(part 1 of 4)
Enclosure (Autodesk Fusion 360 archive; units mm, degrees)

design "BOX" references "IO_BOARD"
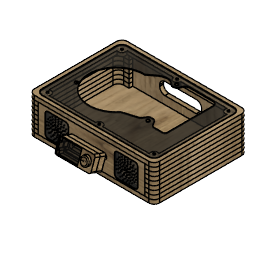
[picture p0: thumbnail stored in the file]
part number: 2026-06-03-19-10-17-454
part number: 2026-06-04-17-30-21-244
part number: 2026-06-04-17-30-21-255
part number: 2026-06-04-17-30-21-260
part number: 2026-06-04-17-30-21-264
part number: 2026-06-04-17-30-21-269
part number: 2026-06-04-17-30-21-274
part number: 2026-06-04-17-30-21-278
part number: 2026-06-04-17-30-21-283
part number: 2026-06-04-17-30-21-289
part number: 2026-06-04-17-30-21-295
part number: 2026-06-04-17-30-21-300
part number: 2026-06-04-17-30-21-306
part number: 2026-06-04-17-30-21-312
part number: 2026-06-04-17-30-21-318
part number: 2026-06-04-17-30-21-324
part number: 2026-06-04-17-30-21-331
part number: 2026-06-04-17-30-21-338
part number: 2026-06-04-17-30-21-345
part number: 2026-06-04-17-30-21-352
parameter "ply" = 11.21
parameter "acrylic" = 2
parameter "viewing" = 70
parameter "top_mount" = 6
parameter "acr_kerf" = 0.75
parameter "prt_tol" = 0.2
sketch "Sketch1" plane through (0, 0, 0) normal (0, 0, 1) x axis (1, 0, 0)
  line L1 (-175, 130) -> (175, 130)
  line L2 (-175, -130) -> (-175, 130)
  line L3 (175, -130) -> (-175, -130)
  line L4 (175, 130) -> (175, -130)
  line L5 (-175, -130) -> (175, 130)
  line L6 (175, -130) -> (-175, 130)
  point P6 (0, 0)
  point P1 (0, 0)
  point P4 (-175, -130)
  point P5 (175, -130)
  point P3 (-175, 130)
  horizontal L1
  perpendicular L1 L2
  parallel L1 L3
  parallel L2 L4
  coincident L5 P6
  coincident L6 P6
  coincident P1 P6
  dimension "d1" distance P4 P5 = 350
  dimension "d2" distance P3 P4 = 260
extrude "Extrude1" new body sketch "Sketch1" profile of L1 L2 L3 L4 along normal blind 11.21 (= "ply") bodies "BOTTOM"
sketch "Sketch2" plane through (0, 0, 11.21) normal (0, 0, 1) x axis (-1, 0, 0)
  line L1 (-175, -130) -> (-175, 130)
  line L2 (175, -130) -> (-175, -130)
  line L3 (175, 130) -> (175, -130)
  line L4 (-175, 130) -> (175, 130)
  line L5 (175, 130) -> (-175, 130)
  line L6 (175, -130) -> (175, 130)
  line L7 (-175, -130) -> (175, -130)
  line L8 (-175, 130) -> (-175, -130)
  line L9 (175, -130) -> (-175, 130)
  line L10 (-175, -130) -> (175, 130)
  line L11 (163.79, 118.79) -> (-163.79, 118.79)
  line L12 (163.79, -118.79) -> (163.79, 118.79)
  line L13 (-163.79, -118.79) -> (163.79, -118.79)
  line L14 (-163.79, 118.79) -> (-163.79, -118.79)
  line L15 (-163.79, -118.79) -> (163.79, -118.79)
  line L16 (-163.79, -108.79) -> (-163.79, -118.79)
  line L17 (163.79, -108.79) -> (-163.79, -108.79)
  line L18 (163.79, -118.79) -> (163.79, -108.79)
  line L19 (-163.79, 118.79) -> (163.79, 118.79)
  line L20 (-163.79, 108.79) -> (-163.79, 118.79)
  line L21 (163.79, 108.79) -> (-163.79, 108.79)
  line L22 (163.79, 118.79) -> (163.79, 108.79)
  line L23 (133.79, -108.79) -> (133.79, -118.79)
  line L24 (0, 130) -> (0, -130)
  line L25 (-175, 0) -> (175, 0)
  line L26 (148.79, -118.79) -> (148.79, -130)
  line L27 (-133.79, -108.79) -> (-133.79, -118.79)
  line L28 (-148.79, -118.79) -> (-148.79, -130)
  line L29 (148.79, 118.79) -> (148.79, 130)
  line L30 (133.79, 108.79) -> (133.79, 118.79)
  line L31 (-148.79, 118.79) -> (-148.79, 130)
  line L32 (-133.79, 108.79) -> (-133.79, 118.79)
  point P10 (0, 0)
  point P2 (-175, 130)
  point P6 (-175, 130)
  point P1 (0, 0)
  point P21 (133.79, -118.79)
  point P22 (133.79, -108.79)
  point P23 (0, -130)
  point P24 (0, 130)
  point P25 (175, 0)
  point P26 (-175, 0)
  point P27 (148.79, -130)
  point P28 (148.79, -118.79)
  point P29 (-133.79, -118.79)
  point P30 (-133.79, -108.79)
  point P31 (-148.79, -130)
  point P32 (-148.79, -118.79)
  point P35 (133.79, 118.79)
  point P36 (133.79, 108.79)
  point P33 (148.79, 130)
  point P34 (148.79, 118.79)
  point P39 (-133.79, 118.79)
  point P40 (-133.79, 108.79)
  point P37 (-148.79, 130)
  point P38 (-148.79, 118.79)
  point P13 (163.79, -118.79)
  point P17 (163.79, -108.79)
  point P12 (163.79, 118.79)
  point P20 (163.79, 108.79)
  horizontal L5
  perpendicular L5 L6
  parallel L5 L7
  parallel L6 L8
  coincident L9 P10
  coincident L10 P10
  coincident P2 P6
  coincident P1 P10
  horizontal L15
  vertical L16
  horizontal L17
  vertical L18
  horizontal L19
  vertical L20
  horizontal L21
  vertical L22
  coincident L13 P21
  coincident L17 P22
  perpendicular L17 L23
  midpoint L7 P23
  midpoint L5 P24
  midpoint L6 P25
  midpoint L8 P26
  collinear L14 L16
  collinear L14 L20
  coincident L7 P27
  coincident L15 P28
  perpendicular L15 L26
  symmetric P21 L24 P29
  symmetric P22 L24 P30
  symmetric L24 P27 P31
  symmetric L24 P28 P32
  symmetric P21 L25 P35
  symmetric P22 L25 P36
  symmetric L25 P27 P33
  symmetric L25 P28 P34
  symmetric L25 P29 P39
  symmetric L25 P30 P40
  symmetric L25 P31 P37
  symmetric L25 P32 P38
  dimension "d6" = 11.21 (= "ply")
  dimension "d7" distance P13 P17 = 10
  dimension "d8" distance P12 P20 = 10
  dimension "d9" distance L18 L23 = 30
  dimension "d10" distance L18 L26 = 15
extrude "Extrude2" new body sketch "Sketch2" profile of L1 L2 L3 L4 L5 L6 L7 L8 L14 L11 L12 L13 L15 L16 L17 L18 L19 L20 L21 L22 L23 L26 L27 L28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 along normal blind 11.21 (= "ply") bodies "L1", "R1"
fillet "Fillet2" radius 15
copy_paste_bodies "CopyPasteBodies1"
move "Move1"
copy_paste_bodies "CopyPasteBodies2"
copy_paste_bodies "CopyPasteBodies3"
move "Move2"
copy_paste_bodies "CopyPasteBodies4"
move "Move3"
copy_paste_bodies "CopyPasteBodies5"
move "Move4"
copy_paste_bodies "CopyPasteBodies6"
move "Move5"
copy_paste_bodies "CopyPasteBodies8"
move "Move7"
sketch "Sketch5" plane through (0, 0, 89.68) normal (0, 0, 1) x axis (-1, 0, 0)
  line L1 (-148.79, -130) -> (-160, -130)
  line L2 (-148.79, -118.79) -> (-148.79, -130)
  line L3 (-133.79, -118.79) -> (-148.79, -118.79)
  line L4 (-133.79, -108.79) -> (-133.79, -118.79)
  line L5 (-148.79, -108.79) -> (-133.79, -108.79)
  line L6 (-163.79, 93.79) -> (-163.79, -93.79)
  line L7 (-133.79, 108.79) -> (-148.79, 108.79)
  line L8 (-133.79, 118.79) -> (-133.79, 108.79)
  line L9 (-148.79, 118.79) -> (-133.79, 118.79)
  line L10 (-148.79, 130) -> (-148.79, 118.79)
  line L11 (-160, 130) -> (-148.79, 130)
  line L12 (-175, -115) -> (-175, 115)
  line L13 (175, 115) -> (175, -115)
  line L14 (148.79, 130) -> (160, 130)
  line L15 (148.79, 118.79) -> (148.79, 130)
  line L16 (133.79, 118.79) -> (148.79, 118.79)
  line L17 (133.79, 108.79) -> (133.79, 118.79)
  line L18 (148.79, 108.79) -> (133.79, 108.79)
  line L19 (163.79, -93.79) -> (163.79, 93.79)
  line L20 (133.79, -108.79) -> (148.79, -108.79)
  line L21 (133.79, -118.79) -> (133.79, -108.79)
  line L22 (148.79, -118.79) -> (133.79, -118.79)
  line L23 (148.79, -130) -> (148.79, -118.79)
  line L24 (160, -130) -> (148.79, -130)
  line L25 (148.79, 118.79) -> (-163, 118.79)
  line L26 (-163.79, 103.79) -> (-163.79, -103.79)
  line L27 (148.79, -118.79) -> (-148.79, -118.79)
  line L28 (163.79, -103.79) -> (163.79, 103.79)
  line L29 (148.79, -130) -> (-148.79, -130)
  line L30 (148.79, -118.79) -> (148.79, -130)
  line L31 (-148.79, -118.79) -> (148.79, -118.79)
  line L32 (-148.79, -130) -> (-148.79, -118.79)
  line L33 (148.79, 118.79) -> (-148.79, 118.79)
  line L34 (148.79, 130) -> (148.79, 118.79)
  line L35 (-148.79, 130) -> (148.79, 130)
  line L36 (-148.79, 118.79) -> (-148.79, 130)
  line L37 (148.79, -108.79) -> (-148.79, -108.79)
  line L38 (153.79, -103.79) -> (153.79, 103.79)
  line L39 (148.79, 108.79) -> (-138.79, 108.79)
  line L40 (-153.79, 93.79) -> (-153.79, -103.79)
  line L41 (0, 130) -> (0, -130)
  arc A1 centre (-160, -115) radius 15 clockwise from (-160, -130) to (-175, -115)
  arc A2 centre (-148.79, -93.79) radius 15 clockwise from (-148.79, -108.79) to (-163.79, -93.79)
  arc A3 centre (-148.79, 93.79) radius 15 clockwise from (-163.79, 93.79) to (-148.79, 108.79)
  arc A4 centre (-160, 115) radius 15 clockwise from (-175, 115) to (-160, 130)
  arc A5 centre (160, -115) radius 15 clockwise from (175, -115) to (160, -130)
  arc A6 centre (160, 115) radius 15 clockwise from (160, 130) to (175, 115)
  arc A7 centre (148.79, 93.79) radius 15 clockwise from (148.79, 108.79) to (163.79, 93.79)
  arc A8 centre (148.79, -93.79) radius 15 clockwise from (163.79, -93.79) to (148.79, -108.79)
  arc A9 centre (-148.79, -103.79) radius 15 clockwise from (-148.79, -118.79) to (-163.79, -103.79)
  arc A10 centre (148.79, -103.79) radius 15 clockwise from (163.79, -103.79) to (148.79, -118.79)
  arc A11 centre (148.79, 103.79) radius 15 clockwise from (148.79, 118.79) to (163.79, 103.79)
  arc A12 centre (148.79, -103.79) radius 5 clockwise from (153.79, -103.79) to (148.79, -108.79)
  arc A13 centre (148.79, 103.79) radius 5 clockwise from (148.79, 108.79) to (153.79, 103.79)
  arc A14 centre (-148.79, -103.79) radius 5 clockwise from (-148.79, -108.79) to (-153.79, -103.79)
  arc A15 centre (-148.79, 103.79) radius 15 clockwise from (-163.79, 103.79) to (-148.79, 118.79)
  arc A16 centre (-138.79, 93.79) radius 15 clockwise from (-153.79, 93.79) to (-138.79, 108.79)
  circle C1 centre (148.79, -103.79) radius 10
  circle C2 centre (148.79, 103.79) radius 10
  circle C3 centre (-148.79, 103.79) radius 10
  circle C4 centre (-148.79, -103.79) radius 10
  circle C5 centre (0, -108.79) radius 10
  circle C6 centre (0, 108.79) radius 10
  point P40 (148.79, -118.79)
  point P45 (148.79, -118.79)
  point P5 (-148.79, -130)
  point P43 (-148.79, -130)
  point P28 (148.79, 130)
  point P49 (148.79, 130)
  point P17 (-148.79, 118.79)
  point P47 (-148.79, 118.79)
  point P79 (0, -130)
  point P80 (0, 130)
  point P81 (0, -108.79)
  point P82 (0, 108.79)
  perpendicular L15 L25
  parallel L6 L26
  collinear L6 L26
  collinear L9 L25
  perpendicular L23 L27
  parallel L13 L28
  collinear L3 L27
  collinear L19 L28
  horizontal L29
  vertical L30
  horizontal L31
  vertical L32
  coincident P40 P45
  coincident P5 P43
  horizontal L33
  vertical L34
  horizontal L35
  vertical L36
  coincident P28 P49
  coincident P17 P47
  tangent L26 A9
  tangent L27 A9
  tangent L27 A10
  tangent L28 A10
  tangent L25 A11
  tangent L28 A11
  equal A10 A11
  concentric A10 A12
  concentric A11 A13
  concentric A9 A14
  tangent L37 A14
  tangent L37 A12
  tangent A12 L38
  tangent L38 A13
  tangent A13 L39
  tangent L40 A14
  coincident P47 L33
  tangent L33 A15
  tangent L26 A15
  equal A10 A15
  tangent L40 A16
  tangent L39 A16
  equal A10 A16
  concentric A12 C1
  concentric A13 C2
  concentric A15 C3
  concentric A9 C4
  midpoint L29 P79
  midpoint L35 P80
  midpoint L37 P81
  coincident L39 P82
  coincident L41 P82
  dimension "d30" radius A9 = 15
  dimension "d31" radius A10 = 15
  dimension "d110" diameter C1 = 20
  dimension "d111" diameter C2 = 20
  dimension "d112" diameter C3 = 20
  dimension "d113" diameter C4 = 20
  dimension "d114" diameter C5 = 20
  dimension "d115" diameter C6 = 20
extrude "Extrude6" new body sketch "Sketch5" profile of A1 L1 L2 L3 L6 L9 L10 L11 A4 L12 A5 L13 A6 L14 L15 L16 L19 L22 L23 L24 L25 L26 L27 L28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 along normal blind 11.21 (= "ply") bodies "TOP"
extrude "Extrude7" add sketch "Sketch5" profile of L3 L4 L5 A2 L6 A3 L7 L8 L9 L16 L17 L18 A7 L19 A8 L20 L21 L22 L25 L26 L27 L28 L37 L38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 along normal blind 9.21 (= "ply - acrylic")
sketch "Sketch6" plane through (0, 0, 98.89) normal (0, 0, 1) x axis (-1, 0, 0)
  line L1 (-10, 108.79) -> (-138.79, 108.79)
  line L2 (-148.79, 118.79) -> (148.79, 118.79)
  line L3 (-163.79, -103.79) -> (-163.79, 103.79)
  line L4 (148.79, -118.79) -> (-148.79, -118.79)
  line L5 (163.79, 103.79) -> (163.79, -103.79)
  line L6 (153.79, -95.1297) -> (153.79, 95.1297)
  line L7 (10, -108.79) -> (140.1297, -108.79)
  line L8 (-153.79, 93.79) -> (-153.79, -95.1297)
  line L9 (140.1297, 108.79) -> (10, 108.79)
  line L10 (-140.1297, -108.79) -> (-10, -108.79)
  arc A1 centre (-148.79, 103.79) radius 15 clockwise from (-163.79, 103.79) to (-148.79, 118.79)
  arc A2 centre (-148.79, -103.79) radius 15 clockwise from (-148.79, -118.79) to (-163.79, -103.79)
  arc A3 centre (148.79, -103.79) radius 15 clockwise from (163.79, -103.79) to (148.79, -118.79)
  arc A4 centre (148.79, 103.79) radius 15 clockwise from (148.79, 118.79) to (163.79, 103.79)
  arc A5 centre (0, 108.79) radius 10 clockwise from (10, 108.79) to (-10, 108.79)
  arc A6 centre (-138.79, 93.79) radius 15 clockwise from (-140.0971, 108.7329) to (-138.79, 108.79)
  arc A7 centre (148.79, 103.79) radius 10 clockwise from (153.79, 95.1297) to (140.1297, 108.79)
  arc A8 centre (148.79, -103.79) radius 10 clockwise from (140.1297, -108.79) to (153.79, -95.1297)
  arc A9 centre (0, -108.79) radius 10 clockwise from (-10, -108.79) to (10, -108.79)
  arc A10 centre (-148.79, -103.79) radius 10 clockwise from (-153.79, -95.1297) to (-140.1297, -108.79)
  arc A11 centre (-138.79, 93.79) radius 15 clockwise from (-153.79, 93.79) to (-153.7329, 95.0971)
  arc A12 centre (-148.79, 103.79) radius 10 clockwise from (-140.0971, 108.7329) to (-153.7329, 95.0971)
extrude "Extrude8" new body sketch "Sketch6" profile of L1 L2 A1 L3 A2 L4 A3 L5 A4 along normal blind 2 (= "acrylic") bodies "ACRYLIC"
sketch "Sketch7" plane through (0, 130, 0) normal (0, 1, 0) x axis (-1, 0, 0)
  line L1 (-160, 78.47) -> (-160, 89.68)
  line L2 (-148.79, 78.47) -> (-160, 78.47)
  line L3 (-148.79, 89.68) -> (-148.79, 78.47)
  line L4 (-148.79, 89.68) -> (-148.79, 78.47)
  line L5 (-148.79, 78.47) -> (-148.79, 67.26)
  line L6 (-148.79, 67.26) -> (-148.79, 56.05)
  line L7 (-148.79, 56.05) -> (-148.79, 44.84)
  line L8 (-148.79, 44.84) -> (-148.79, 33.63)
  line L9 (-148.79, 33.63) -> (-148.79, 22.42)
  line L10 (-148.79, 22.42) -> (-148.79, 11.21)
  line L11 (160, 89.68) -> (-160, 89.68)
  line L12 (160, 11.21) -> (-160, 11.21)
  line L13 (148.79, 33.63) -> (148.79, 22.42)
  line L14 (148.79, 44.84) -> (148.79, 33.63)
  line L15 (148.79, 56.05) -> (148.79, 44.84)
  line L16 (148.79, 67.26) -> (148.79, 56.05)
  line L17 (148.79, 78.47) -> (148.79, 67.26)
  line L18 (148.79, 89.68) -> (148.79, 78.47)
  line L19 (148.79, 22.42) -> (148.79, 11.21)
  line L20 (148.79, 89.68) -> (-148.79, 89.68)
  line L21 (148.79, 11.21) -> (148.79, 89.68)
  line L22 (-148.79, 11.21) -> (148.79, 11.21)
  line L23 (-148.79, 89.68) -> (-148.79, 11.21)
  line L24 (43.75, 69.945) -> (-43.75, 69.945)
  line L25 (61, 48.195) -> (61, 52.695)
  line L26 (-43.75, 30.945) -> (43.75, 30.945)
  line L27 (-61, 52.695) -> (-61, 48.195)
  line L28 (43.75, 67.445) -> (-43.75, 67.445)
  line L29 (-58.5, 52.695) -> (-58.5, 48.195)
  line L30 (-43.75, 33.445) -> (43.75, 33.445)
  line L31 (58.5, 48.195) -> (58.5, 52.695)
  line L32 (0, 30.945) -> (0, 69.945)
  line L33 (61, 50.445) -> (-61, 50.445)
  line L34 (0, 11.21) -> (0, 89.68)
  line L35 (148.79, 50.445) -> (-148.79, 50.445)
  line L36 (-160, 89.68) -> (-148.79, 89.68)
  arc A1 centre (-43.75, 48.195) radius 17.25 clockwise from (-43.75, 30.945) to (-61, 48.195)
  arc A2 centre (43.75, 48.195) radius 17.25 clockwise from (61, 48.195) to (43.75, 30.945)
  arc A3 centre (43.75, 52.695) radius 17.25 clockwise from (43.75, 69.945) to (61, 52.695)
  arc A4 centre (-43.75, 52.695) radius 17.25 clockwise from (-61, 52.695) to (-43.75, 69.945)
  arc A5 centre (43.75, 52.695) radius 14.75 clockwise from (43.75, 67.445) to (58.5, 52.695)
  arc A6 centre (-43.75, 52.695) radius 14.75 clockwise from (-58.5, 52.695) to (-43.75, 67.445)
  arc A7 centre (-43.75, 48.195) radius 14.75 clockwise from (-43.75, 33.445) to (-58.5, 48.195)
  arc A8 centre (43.75, 48.195) radius 14.75 clockwise from (58.5, 48.195) to (43.75, 33.445)
  point P36 (148.79, 11.21)
  point P40 (148.79, 11.21)
  point P7 (-148.79, 89.68)
  point P38 (-148.79, 89.68)
  point P44 (-61, 30.945)
  point P43 (61, 69.945)
  point P42 (-61, 69.945)
  point P69 (0, 69.945)
  point P70 (0, 30.945)
  point P71 (-61, 50.445)
  point P72 (61, 50.445)
  point P73 (0, 89.68)
  point P74 (0, 11.21)
  point P75 (-148.79, 50.445)
  point P76 (148.79, 50.445)
  point P77 (0, 50.445)
  point P78 (0, 50.445)
  horizontal L20
  vertical L21
  horizontal L22
  vertical L23
  coincident P36 P40
  coincident P7 P38
  horizontal L24
  vertical L25
  horizontal L26
  vertical L27
  coincident P44 L26
  coincident P44 L27
  tangent L26 A1
  tangent L27 A1
  tangent L25 A2
  tangent L26 A2
  equal A1 A2
  coincident P43 L24
  coincident P43 L25
  tangent L24 A3
  tangent L25 A3
  equal A1 A3
  coincident P42 L24
  coincident P42 L27
  tangent L24 A4
  tangent L27 A4
  equal A1 A4
  midpoint L24 P69
  midpoint L26 P70
  midpoint L27 P71
  midpoint L25 P72
  midpoint L20 P73
  midpoint L12 P74
  midpoint L7 P75
  midpoint L15 P76
  midpoint L32 P77
  midpoint L34 P78
  coincident P77 P78
  dimension "d42" distance P42 P43 = 122
  dimension "d43" distance P42 P44 = 39
  dimension "d44" radius A1 = 17.25
  dimension "d45" = 2.5
extrude "Extrude9" new body sketch "Sketch7" profile of L3 L4 L5 L6 L7 L8 L9 L10 L11 L12 L13 L14 L15 L16 L17 L18 L19 L20 L21 L22 L23 L24 L25 L26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 no distance stored bodies "BACK"
sketch "Sketch8" plane through (0, -118.79, 0) normal (0, -1, 0) x axis (1, 0, 0)
  line L1 (-133.79, 78.47) -> (-148.79, 78.47)
  line L2 (-133.79, 89.68) -> (-133.79, 78.47)
  line L3 (-148.79, 78.47) -> (-148.79, 89.68)
  line L4 (160, 89.68) -> (-160, 89.68)
  line L5 (-148.79, 78.47) -> (-148.79, 67.26)
  line L6 (-148.79, 67.26) -> (-148.79, 56.05)
  line L7 (-148.79, 56.05) -> (-148.79, 44.84)
  line L8 (-148.79, 44.84) -> (-148.79, 33.63)
  line L9 (-148.79, 33.63) -> (-148.79, 22.42)
  line L10 (-148.79, 22.42) -> (-148.79, 11.21)
  line L11 (148.79, 89.68) -> (148.79, 78.47)
  line L12 (148.79, 78.47) -> (148.79, 67.26)
  line L13 (148.79, 67.26) -> (148.79, 56.05)
  line L14 (148.79, 56.05) -> (148.79, 44.84)
  line L15 (148.79, 44.84) -> (148.79, 33.63)
  line L16 (148.79, 33.63) -> (148.79, 22.42)
  line L17 (148.79, 22.42) -> (148.79, 11.21)
  line L18 (160, 11.21) -> (-160, 11.21)
  line L19 (-148.79, 89.68) -> (-148.79, 78.47)
  line L20 (148.79, 89.68) -> (-148.79, 89.68)
  line L21 (148.79, 11.21) -> (148.79, 89.68)
  line L22 (-148.79, 11.21) -> (148.79, 11.21)
  line L23 (-148.79, 89.68) -> (-148.79, 11.21)
  line L24 (-128.79, 79.68) -> (-64.79, 79.68)
  line L25 (-128.79, 15.68) -> (-128.79, 79.68)
  line L26 (-64.79, 15.68) -> (-128.79, 15.68)
  line L27 (-64.79, 79.68) -> (-64.79, 15.68)
  line L28 (-128.79, 15.68) -> (-64.79, 79.68)
  line L29 (-64.79, 15.68) -> (-128.79, 79.68)
  line L30 (0, 11.21) -> (0, 89.68)
  line L31 (128.79, 79.68) -> (64.79, 79.68)
  line L32 (128.79, 15.68) -> (128.79, 79.68)
  line L33 (64.79, 15.68) -> (128.79, 15.68)
  line L34 (64.79, 79.68) -> (64.79, 15.68)
  line L35 (64.79, 15.68) -> (128.79, 79.68)
  line L36 (128.79, 15.68) -> (64.79, 79.68)
  line L37 (42.5, 42.945) -> (-42.5, 42.945)
  line L38 (42.5, 57.945) -> (42.5, 42.945)
  line L39 (-42.5, 57.945) -> (42.5, 57.945)
  line L40 (-42.5, 42.945) -> (-42.5, 57.945)
  line L41 (42.5, 57.945) -> (-42.5, 42.945)
  line L42 (42.5, 42.945) -> (-42.5, 57.945)
  line L43 (-148.79, 89.68) -> (-133.79, 89.68)
  point P32 (148.79, 11.21)
  point P40 (148.79, 11.21)
  point P37 (-148.79, 89.68)
  point P38 (-148.79, 89.68)
  point P46 (-96.79, 47.68)
  point P47 (0, 89.68)
  point P48 (0, 11.21)
  point P42 (-64.79, 79.68)
  point P50 (64.79, 79.68)
  point P43 (-128.79, 79.68)
  point P51 (128.79, 79.68)
  point P44 (-128.79, 15.68)
  point P52 (128.79, 15.68)
  point P45 (-64.79, 15.68)
  point P53 (64.79, 15.68)
  point P49 (96.79, 47.68)
  point P58 (0, 50.445)
  point P59 (0, 50.445)
  point P54 (-42.5, 42.945)
  point P55 (42.5, 42.945)
  point P57 (-42.5, 57.945)
  horizontal L20
  vertical L21
  horizontal L22
  vertical L23
  coincident P32 P40
  coincident P37 P38
  horizontal L24
  perpendicular L24 L25
  parallel L24 L26
  parallel L25 L27
  coincident L28 P46
  coincident L29 P46
  midpoint L4 P47
  midpoint L18 P48
  symmetric P42 L30 P50
  symmetric P43 L30 P51
  symmetric P44 L30 P52
  symmetric P45 L30 P53
  symmetric P46 L30 P49
  horizontal L37
  vertical L38
  horizontal L39
  vertical L40
  midpoint L41 P58
  midpoint L30 P59
  coincident P58 P59
  dimension "d48" distance P44 P45 = 64
  dimension "d49" distance P43 P44 = 64
  dimension "d50" distance L20 L24 = 10
  dimension "d51" distance L23 L25 = 20
  dimension "d52" distance P54 P55 = 85
  dimension "d53" distance P54 P57 = 15
extrude "Extrude10" new body sketch "Sketch8" profile of L1 L2 L3 L4 L5 L6 L7 L8 L9 L10 L11 L12 L13 L14 L15 L16 L17 L18 L19 L20 L21 L22 L23 L24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 along normal blind 11.21 (= "ply") bodies "FRONT"
fillet "Fillet3" radius 7.5
fillet "Fillet4" radius 7.5
sketch "Sketch9" plane through (0, 0, 100.89) normal (0, 0, 1) x axis (-1, 0, 0)
  line L1 (-148.79, 118.79) -> (148.79, 118.79)
  line L2 (-163.79, -103.79) -> (-163.79, 103.79)
  line L3 (148.79, -118.79) -> (-148.79, -118.79)
  line L4 (163.79, 103.79) -> (163.79, -103.79)
  line L5 (-148.0004, -118.79) -> (148.79, -118.79)
  line L6 (-148.0004, -106.79) -> (-148.0004, -118.79)
  line L7 (148.79, -106.79) -> (-148.0004, -106.79)
  line L8 (148.79, -118.79) -> (148.79, -106.79)
  line L9 (-115.79, 103.79) -> (-163.79, 103.79)
  line L10 (-115.79, -94.0016) -> (-115.79, 103.79)
  line L11 (-163.79, -106.0016) -> (-115.79, -106.0016)
  line L12 (-163.79, 103.79) -> (-163.79, -106.0016)
  curve K1 (135.0682, -7.9271) -> (135.2565, -4.5559)
  curve K2 (134.8095, -10.0484) -> (135.0682, -7.9271)
  curve K3 (134.5502, -12.0089) -> (134.8095, -10.0484)
  curve K4 (134.2426, -13.9345) -> (134.5502, -12.0089)
  curve K5 (134.0561, -14.8833) -> (134.2426, -13.9345)
  curve K6 (133.0741, -19.2216) -> (134.0561, -14.8833)
  curve K7 (132.7951, -20.3322) -> (133.0741, -19.2216)
  curve K8 (129.1502, -30.6896) -> (132.7951, -20.3322)
  curve K9 (126.1595, -36.6558) -> (129.1502, -30.6896)
  curve K10 (124.992, -38.5911) -> (126.1595, -36.6558)
  curve K11 (121.3046, -44.1767) -> (124.992, -38.5911)
  curve K12 (120.6044, -45.1367) -> (121.3046, -44.1767)
  curve K13 (117.2417, -49.3245) -> (120.6044, -45.1367)
  curve K14 (116.2247, -50.4492) -> (117.2417, -49.3245)
  curve K15 (113.142, -53.6965) -> (116.2247, -50.4492)
  curve K16 (109.7202, -56.8033) -> (113.142, -53.6965)
  curve K17 (104.5726, -60.7916) -> (109.7202, -56.8033)
  curve K18 (104.1694, -61.0824) -> (104.5726, -60.7916)
  curve K19 (102.8748, -61.974) -> (104.1694, -61.0824)
  curve K20 (100.0986, -63.7395) -> (102.8748, -61.974)
  curve K21 (99.6142, -64.0994) -> (100.0986, -63.7395)
  curve K22 (98.6752, -64.6628) -> (99.6142, -64.0994)
  curve K23 (97.6049, -65.2601) -> (98.6752, -64.6628)
  curve K24 (92.1824, -68.0515) -> (97.6049, -65.2601)
  curve K25 (90.8673, -68.6184) -> (92.1824, -68.0515)
  curve K26 (86.6763, -70.2774) -> (90.8673, -68.6184)
  curve K27 (85.5501, -70.6756) -> (86.6763, -70.2774)
  curve K28 (81.7042, -71.8595) -> (85.5501, -70.6756)
  curve K29 (79.3351, -72.4619) -> (81.7042, -71.8595)
  curve K30 (78.4042, -72.6907) -> (79.3351, -72.4619)
  curve K31 (75.3126, -73.3016) -> (78.4042, -72.6907)
  curve K32 (73.7026, -73.5896) -> (75.3126, -73.3016)
  curve K33 (72.3464, -73.8076) -> (73.7026, -73.5896)
  curve K34 (71.8804, -73.8904) -> (72.3464, -73.8076)
  curve K35 (70.806, -74.0158) -> (71.8804, -73.8904)
  curve K36 (69.6278, -74.1696) -> (70.806, -74.0158)
  curve K37 (69.2955, -74.2183) -> (69.6278, -74.1696)
  curve K38 (68.4797, -74.2733) -> (69.2955, -74.2183)
  curve K39 (60.5422, -74.5346) -> (68.4797, -74.2733)
  curve K40 (56.667, -74.8007) -> (60.5422, -74.5346)
  curve K41 (56.3412, -74.9334) -> (56.667, -74.8007)
  curve K42 (55.5427, -75.4144) -> (56.3412, -74.9334)
  curve K43 (54.4526, -76.2092) -> (55.5427, -75.4144)
  curve K44 (52.8188, -77.4736) -> (54.4526, -76.2092)
  curve K45 (51.8551, -78.2092) -> (52.8188, -77.4736)
  curve K46 (50.8913, -78.9439) -> (51.8551, -78.2092)
  curve K47 (50.2208, -79.4513) -> (50.8913, -78.9439)
  curve K48 (49.5077, -79.9488) -> (50.2208, -79.4513)
  curve K49 (47.435, -81.5036) -> (49.5077, -79.9488)
  curve K50 (46.1128, -82.4891) -> (47.435, -81.5036)
  curve K51 (44.4879, -83.6859) -> (46.1128, -82.4891)
  curve K52 (42.7695, -84.9709) -> (44.4879, -83.6859)
  curve K53 (41.3343, -86.0389) -> (42.7695, -84.9709)
  curve K54 (40.254, -86.823) -> (41.3343, -86.0389)
  curve K55 (39.5727, -87.3258) -> (40.254, -86.823)
  curve K56 (39.1855, -87.6126) -> (39.5727, -87.3258)
  curve K57 (38.0225, -88.479) -> (39.1855, -87.6126)
  curve K58 (37.0235, -89.2178) -> (38.0225, -88.479)
  curve K59 (37.028, -89.2836) -> (37.0235, -89.2178)
  curve K60 (38.9653, -88.0285) -> (37.028, -89.2836)
  curve K61 (40.5617, -86.8905) -> (38.9653, -88.0285)
  curve K62 (41.6774, -86.0469) -> (40.5617, -86.8905)
  curve K63 (42.4173, -85.486) -> (41.6774, -86.0469)
  curve K64 (42.7062, -85.3799) -> (42.4173, -85.486)
  curve K65 (42.8517, -85.3225) -> (42.7062, -85.3799)
  curve K66 (41.4453, -86.5641) -> (42.8517, -85.3225)
  curve K67 (39.4627, -88.0469) -> (41.4453, -86.5641)
  curve K68 (39.2843, -88.1816) -> (39.4627, -88.0469)
  curve K69 (38.5605, -88.6925) -> (39.2843, -88.1816)
  curve K70 (37.208, -89.696) -> (38.5605, -88.6925)
  curve K71 (36.2713, -90.3859) -> (37.208, -89.696)
  curve K72 (35.3504, -91.02) -> (36.2713, -90.3859)
  curve K73 (34.0186, -91.8956) -> (35.3504, -91.02)
  curve K74 (33.1239, -92.4654) -> (34.0186, -91.8956)
  curve K75 (32.4515, -92.861) -> (33.1239, -92.4654)
  curve K76 (31.3968, -93.3779) -> (32.4515, -92.861)
  curve K77 (30.5136, -93.7443) -> (31.3968, -93.3779)
  curve K78 (28.4474, -94.625) -> (30.5136, -93.7443)
  curve K79 (26.9701, -95.1807) -> (28.4474, -94.625)
  curve K80 (25.7715, -95.5912) -> (26.9701, -95.1807)
  curve K81 (21.5139, -96.634) -> (25.7715, -95.5912)
  curve K82 (19.2668, -96.9464) -> (21.5139, -96.634)
  curve K83 (18.5638, -97.0402) -> (19.2668, -96.9464)
  curve K84 (13.2773, -97.1902) -> (18.5638, -97.0402)
  curve K85 (9.9554, -96.8745) -> (13.2773, -97.1902)
  curve K86 (9.3588, -96.7955) -> (9.9554, -96.8745)
  curve K87 (5.6844, -95.8337) -> (9.3588, -96.7955)
  curve K88 (4.9541, -95.434) -> (5.6844, -95.8337)
  curve K89 (3.707, -94.6868) -> (4.9541, -95.434)
  curve K90 (2.7603, -94.0907) -> (3.707, -94.6868)
  curve K91 (2.3915, -93.8419) -> (2.7603, -94.0907)
  curve K92 (1.744, -93.3215) -> (2.3915, -93.8419)
  curve K93 (-2.6931, -89.0142) -> (1.744, -93.3215)
  curve K94 (-3.2416, -88.4145) -> (-2.6931, -89.0142)
  curve K95 (-3.9306, -87.9503) -> (-3.2416, -88.4145)
  curve K96 (-4.0745, -87.9133) -> (-3.9306, -87.9503)
  curve K97 (-5.9088, -86.3118) -> (-4.0745, -87.9133)
  curve K98 (-11.2799, -84.5912) -> (-5.9088, -86.3118)
  curve K99 (-15.2713, -84.8331) -> (-11.2799, -84.5912)
  curve K100 (-17.973, -85.8302) -> (-15.2713, -84.8331)
  curve K101 (-18.4263, -86.0881) -> (-17.973, -85.8302)
  curve K102 (-20.0177, -87.2064) -> (-18.4263, -86.0881)
  curve K103 (-20.7794, -87.8839) -> (-20.0177, -87.2064)
  curve K104 (-23.321, -91.1242) -> (-20.7794, -87.8839)
  curve K105 (-24.2048, -93.4753) -> (-23.321, -91.1242)
  curve K106 (-24.7035, -94.7606) -> (-24.2048, -93.4753)
  curve K107 (-24.8931, -95.2744) -> (-24.7035, -94.7606)
  curve K108 (-27.2302, -99.4375) -> (-24.8931, -95.2744)
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  point P11 (148.79, -118.79)
  point P14 (148.79, -118.79)
  point P6 (-163.79, 103.79)
  point P18 (-163.79, 103.79)
  point P115 (-2.6931, -89.0142)
  point P901 (-2.6931, -89.0142)
  point P92 (37.208, -89.696)
  point P904 (37.208, -89.696)
  point P20 (-115.79, -106.0016)
  point P930 (-2.1639, -89.7249)
  point P931 (-24.9728, -95.5745)
  point P17 (148.79, -106.79)
  point P19 (-115.79, 103.79)
  horizontal L5
  vertical L6
  horizontal L7
  vertical L8
  coincident P11 P14
  horizontal L9
  vertical L10
  horizontal L11
  vertical L12
  coincident P6 P18
  coincident P115 P901
  coincident P92 P904
  coincident P20 L10
  coincident K93 P930
  coincident K108 P931
  dimension "d60" distance P14 P17 = 12
  dimension "d61" distance P18 P19 = 48
  dimension "d62" radius = 12
  dimension "d63" radius = 6.5
  dimension "d64" radius = 14.5
  dimension "d65" radius = 8.15
  dimension "d66" radius = 9
  dimension "d67" radius = 8
  dimension "d68" radius = 8.5
sketch "Sketch10" plane through (0, 0, 100.89) normal (0, 0, 1) x axis (-1, 0, 0)
  curve K1 (-2.6931, -89.0142) -> (33.6145, -91.6878)
  line L1 (33.6145, -91.6878) -> (56.037, -74.7812)
  line L2 (-39.0028, -106.0016) -> (-103.79, -106.0016)
  line L3 (-109.29, 40.651) -> (-84.7008, 40.651)
  line L4 (-77.9184, 36.8936) -> (-70.4881, 25.0153)
  line L5 (-62.858, 20.7882) -> (-57.3532, 20.7882)
  line L6 (-50.4482, 24.6087) -> (-44.6522, 33.8527)
  line L7 (-39.979, 37.4526) -> (-0.9873, 49.5999)
  line L8 (-115.79, -106.0016) -> (-115.79, 34.151)
  arc A1 centre (58.7121, 1.7076) radius 76.5356 clockwise from (-0.9873, 49.5999) to (55.7365, -74.7701)
  arc A2 centre (-12.4884, -96.8605) radius 12.5504 clockwise from (-24.9728, -95.5745) to (-2.1639, -89.7249)
  arc A3 centre (-39.0028, -91.5016) radius 14.5 clockwise from (-24.5028, -91.5017) to (-39.0028, -106.0016)
  arc A4 centre (-103.79, -94.0016) radius 12 clockwise from (-103.79, -106.0016) to (-115.79, -94.0016)
  arc A5 centre (-109.29, 34.151) radius 6.5 clockwise from (-115.79, 34.151) to (-109.29, 40.651)
  arc A6 centre (-84.7008, 32.651) radius 8 clockwise from (-84.7008, 40.651) to (-77.9184, 36.8936)
  arc A7 centre (-62.858, 29.7882) radius 9 clockwise from (-62.858, 20.7882) to (-70.4881, 25.0153)
  arc A8 centre (-57.3532, 28.9382) radius 8.15 clockwise from (-50.4482, 24.6087) to (-57.3532, 20.7882)
  arc A9 centre (-37.4507, 29.3373) radius 8.5 clockwise from (-44.6522, 33.8527) to (-39.979, 37.4526)
extrude "Extrude11" cut sketch "Sketch10" against normal blind 6
sketch "Sketch11" plane through (0, 130, 0) normal (0, 1, 0) x axis (-1, 0, 0)
  line L1 (43.75, 67.445) -> (-43.75, 67.445)
  line L2 (58.5, 48.195) -> (58.5, 52.695)
  line L3 (-43.75, 33.445) -> (43.75, 33.445)
  line L4 (-58.5, 52.695) -> (-58.5, 48.195)
  line L5 (148.79, 11.21) -> (-148.79, 11.21)
  line L6 (148.79, 89.68) -> (148.79, 11.21)
  line L7 (-148.79, 89.68) -> (148.79, 89.68)
  line L8 (-148.79, 11.21) -> (-148.79, 89.68)
  arc A1 centre (-43.75, 52.695) radius 14.75 clockwise from (-58.5, 52.695) to (-43.75, 67.445)
  arc A2 centre (43.75, 52.695) radius 14.75 clockwise from (43.75, 67.445) to (58.5, 52.695)
  arc A3 centre (43.75, 48.195) radius 14.75 clockwise from (58.5, 48.195) to (43.75, 33.445)
  arc A4 centre (-43.75, 48.195) radius 14.75 clockwise from (-43.75, 33.445) to (-58.5, 48.195)
sketch "Sketch12" plane through (0, -118.79, 0) normal (0, 1, 0) x axis (-1, 0, 0)
  line L1 (-128.79, 72.18) -> (-128.79, 23.18)
  line L2 (-72.29, 79.68) -> (-121.29, 79.68)
  line L3 (-64.79, 23.18) -> (-64.79, 72.18)
  line L4 (-121.29, 15.68) -> (-72.29, 15.68)
  line L5 (-35, 42.945) -> (35, 42.945)
  line L6 (35, 57.945) -> (-35, 57.945)
  line L7 (121.29, 79.68) -> (72.29, 79.68)
  line L8 (128.79, 23.18) -> (128.79, 72.18)
  line L9 (72.29, 15.68) -> (121.29, 15.68)
  line L10 (64.79, 72.18) -> (64.79, 23.18)
  line L11 (148.79, 11.21) -> (-148.79, 11.21)
  line L12 (148.79, 89.68) -> (148.79, 11.21)
  line L13 (-148.79, 89.68) -> (148.79, 89.68)
  line L14 (-148.79, 11.21) -> (-148.79, 89.68)
  line L15 (-72.29, 74.68) -> (-121.29, 74.68)
  line L16 (-123.79, 72.18) -> (-123.79, 23.18)
  line L17 (-121.29, 20.68) -> (-72.29, 20.68)
  line L18 (-69.79, 23.18) -> (-69.79, 72.18)
  line L19 (121.29, 74.68) -> (72.29, 74.68)
  line L20 (69.79, 72.18) -> (69.79, 23.18)
  line L21 (72.29, 20.68) -> (121.29, 20.68)
  line L22 (123.79, 23.18) -> (123.79, 72.18)
  arc A1 centre (-121.29, 23.18) radius 7.5 clockwise from (-121.29, 15.68) to (-128.79, 23.18)
  arc A2 centre (-121.29, 72.18) radius 7.5 clockwise from (-128.79, 72.18) to (-121.29, 79.68)
  arc A3 centre (-72.29, 72.18) radius 7.5 clockwise from (-72.29, 79.68) to (-64.79, 72.18)
  arc A4 centre (-72.29, 23.18) radius 7.5 clockwise from (-64.79, 23.18) to (-72.29, 15.68)
  arc A5 centre (35, 50.445) radius 7.5 clockwise from (35, 57.945) to (35, 42.945)
  arc A6 centre (-35, 50.445) radius 7.5 clockwise from (-35, 42.945) to (-35, 57.945)
  arc A7 centre (72.29, 72.18) radius 7.5 clockwise from (64.79, 72.18) to (72.29, 79.68)
  arc A8 centre (121.29, 72.18) radius 7.5 clockwise from (121.29, 79.68) to (128.79, 72.18)
  arc A9 centre (121.29, 23.18) radius 7.5 clockwise from (128.79, 23.18) to (121.29, 15.68)
  arc A10 centre (72.29, 23.18) radius 7.5 clockwise from (72.29, 15.68) to (64.79, 23.18)
  arc A11 centre (-72.29, 72.18) radius 2.5 clockwise from (-72.29, 74.68) to (-69.79, 72.18)
  arc A12 centre (-121.29, 72.18) radius 2.5 clockwise from (-123.79, 72.18) to (-121.29, 74.68)
  arc A13 centre (-121.29, 23.18) radius 2.5 clockwise from (-121.29, 20.68) to (-123.79, 23.18)
  arc A14 centre (-72.29, 23.18) radius 2.5 clockwise from (-69.79, 23.18) to (-72.29, 20.68)
  arc A15 centre (121.29, 72.18) radius 2.5 clockwise from (121.29, 74.68) to (123.79, 72.18)
  arc A16 centre (72.29, 72.18) radius 2.5 clockwise from (69.79, 72.18) to (72.29, 74.68)
  arc A17 centre (72.29, 23.18) radius 2.5 clockwise from (72.29, 20.68) to (69.79, 23.18)
  arc A18 centre (121.29, 23.18) radius 2.5 clockwise from (123.79, 23.18) to (121.29, 20.68)
  dimension "d71" = 5
  dimension "d72" = 5
extrude "Extrude12" add sketch "Sketch12" profile of A1 L1 A2 L2 A3 L3 A4 L4 A7 L7 A8 L8 A9 L9 A10 L10 A11 L15 A12 L16 A13 L17 A14 L18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 against normal blind 6
sketch "Sketch13" plane through (0, -130, 0) normal (0, -1, 0) x axis (1, 0, 0)
  line L1 (72.29, 15.68) -> (121.29, 15.68)
  line L2 (64.79, 72.18) -> (64.79, 23.18)
  line L3 (121.29, 79.68) -> (72.29, 79.68)
  line L4 (128.79, 23.18) -> (128.79, 72.18)
  line L5 (35, 57.945) -> (-35, 57.945)
  line L6 (-35, 42.945) -> (35, 42.945)
  line L7 (-64.79, 23.18) -> (-64.79, 72.18)
  line L8 (-121.29, 15.68) -> (-72.29, 15.68)
  line L9 (-128.79, 72.18) -> (-128.79, 23.18)
  line L10 (-72.29, 79.68) -> (-121.29, 79.68)
  line L11 (148.79, 11.21) -> (-148.79, 11.21)
  line L12 (148.79, 89.68) -> (148.79, 11.21)
  line L13 (-148.79, 89.68) -> (148.79, 89.68)
  line L14 (-148.79, 11.21) -> (-148.79, 89.68)
  line L15 (35, 57.945) -> (-35, 57.945)
  line L16 (-35, 42.945) -> (35, 42.945)
  arc A1 centre (72.29, 23.18) radius 7.5 clockwise from (72.29, 15.68) to (64.79, 23.18)
  arc A2 centre (72.29, 72.18) radius 7.5 clockwise from (64.79, 72.18) to (72.29, 79.68)
  arc A3 centre (121.29, 72.18) radius 7.5 clockwise from (121.29, 79.68) to (128.79, 72.18)
  arc A4 centre (121.29, 23.18) radius 7.5 clockwise from (128.79, 23.18) to (121.29, 15.68)
  arc A5 centre (-35, 50.445) radius 7.5 clockwise from (-35, 42.945) to (-35, 57.945)
  arc A6 centre (35, 50.445) radius 7.5 clockwise from (35, 57.945) to (35, 42.945)
  arc A7 centre (-72.29, 23.18) radius 7.5 clockwise from (-64.79, 23.18) to (-72.29, 15.68)
  arc A8 centre (-121.29, 23.18) radius 7.5 clockwise from (-121.29, 15.68) to (-128.79, 23.18)
  arc A9 centre (-121.29, 72.18) radius 7.5 clockwise from (-128.79, 72.18) to (-121.29, 79.68)
  arc A10 centre (-72.29, 72.18) radius 7.5 clockwise from (-72.29, 79.68) to (-64.79, 72.18)
  arc A11 centre (35, 50.445) radius 7.5 clockwise from (35, 57.945) to (35, 42.945)
  arc A12 centre (-35, 50.445) radius 7.5 clockwise from (-35, 42.945) to (-35, 57.945)
extrude "Extrude13" new body sketch "Sketch13" profile of A5 L5 A6 L6 L15 A11 L16 A12 along normal blind 20
sketch "Sketch16" plane through (0, -150, 0) normal (0, -1, 0) x axis (1, 0, 0)
  line L1 (-35, 57.945) -> (35, 57.945)
  line L2 (35, 42.945) -> (-35, 42.945)
  line L3 (42.5, 50.445) -> (-42.5, 50.445)
  arc A1 centre (35, 50.445) radius 7.5 clockwise from (35, 57.945) to (35, 42.945)
  arc A2 centre (-35, 50.445) radius 7.5 clockwise from (-35, 42.945) to (-35, 57.945)
  point P8 (-42.5, 50.445)
  point P9 (42.5, 50.445)
  midpoint A2 P8
  midpoint A1 P9
work_plane "WorkPlane2" RotateAngle 70 (= "viewing")
sketch "Sketch17" plane through (0, -148.666, 54.11) normal (0, -0.9397, 0.342) x axis (1, 0, 0)
  line L1 (50, 11.0998) -> (-50, 11.0998)
  line L2 (50, -18.9002) -> (50, 11.0998)
  line L3 (-50, -18.9002) -> (50, -18.9002)
  line L4 (-50, 11.0998) -> (-50, -18.9002)
  line L5 (50, -3.9002) -> (-50, -3.9002)
  line L6 (42.5, -3.9002) -> (-42.5, -3.9002)
  point P6 (-50, -3.9002)
  point P7 (50, -3.9002)
  point P2 (-50, 11.0998)
  point P3 (50, 11.0998)
  point P5 (-50, -18.9002)
  horizontal L1
  vertical L2
  horizontal L3
  vertical L4
  midpoint L4 P6
  midpoint L2 P7
  midpoint L5 L6
  dimension "d87" distance P2 P3 = 100
  dimension "d88" distance P2 P5 = 30
work_plane "WorkPlane3" RotateAngle 70 (= "viewing")
sketch "Sketch18" plane through (0, -146.2556, 53.2327) normal (0, -0.9397, 0.342) x axis (1, 0, 0)
  line L1 (50, 11.0998) -> (-50, 11.0998)
  line L2 (-50, 11.0998) -> (-50, -18.9002)
  line L3 (-50, -18.9002) -> (50, -18.9002)
  line L4 (50, -18.9002) -> (50, 11.0998)
extrude "Extrude15" add sketch "Sketch18" along normal blind 30
fillet "Fillet6" radius 5
sketch "Sketch19" plane through (0, -130, 0) normal (0, 1, 0) x axis (-1, 0, 0)
  line L1 (35, 42.945) -> (-35, 42.945)
  line L2 (-35, 57.945) -> (35, 57.945)
  line L3 (35, 45.945) -> (-35, 45.945)
  line L4 (-35, 54.945) -> (35, 54.945)
  arc A1 centre (-35, 50.445) radius 7.5 clockwise from (-35, 42.945) to (-35, 57.945)
  arc A2 centre (35, 50.445) radius 7.5 clockwise from (35, 57.945) to (35, 42.945)
  arc A3 centre (35, 50.445) radius 4.5 clockwise from (35, 54.945) to (35, 45.945)
  arc A4 centre (-35, 50.445) radius 4.5 clockwise from (-35, 45.945) to (-35, 54.945)
  dimension "d95" = -3
extrude "Extrude16" cut sketch "Sketch19" profile of L4 L3 A3 A4 against normal blind 20
work_plane "WorkPlane4" AlongDistance -15
split "Split1"
extrude "Extrude17" cut of existing geometry blind -3.743
sketch "Sketch20" plane through (0, -160.351, 58.363) normal (0, 0.9397, -0.342) x axis (-1, 0, 0)
  line L1 (50, 6.0998) -> (50, -13.9002)
  line L2 (-45, 11.0998) -> (45, 11.0998)
  line L3 (-50, -13.9002) -> (-50, 6.0998)
  line L4 (45, -18.9002) -> (-45, -18.9002)
  line L5 (-47, -13.9002) -> (-47, 6.0998)
  line L6 (45, -15.9002) -> (-45, -15.9002)
  line L7 (47, 6.0998) -> (47, -13.9002)
  line L8 (-45, 8.0998) -> (45, 8.0998)
  arc A1 centre (45, -13.9002) radius 5 clockwise from (50, -13.9002) to (45, -18.9002)
  arc A2 centre (45, 6.0998) radius 5 clockwise from (45, 11.0998) to (50, 6.0998)
  arc A3 centre (-45, 6.0998) radius 5 clockwise from (-50, 6.0998) to (-45, 11.0998)
  arc A4 centre (-45, -13.9002) radius 5 clockwise from (-45, -18.9002) to (-50, -13.9002)
  arc A5 centre (-45, -13.9002) radius 2 clockwise from (-45, -15.9002) to (-47, -13.9002)
  arc A6 centre (45, -13.9002) radius 2 clockwise from (47, -13.9002) to (45, -15.9002)
  arc A7 centre (45, 6.0998) radius 2 clockwise from (45, 8.0998) to (47, 6.0998)
  arc A8 centre (-45, 6.0998) radius 2 clockwise from (-47, 6.0998) to (-45, 8.0998)
  dimension "d101" = -3
extrude "Extrude18" cut sketch "Sketch20" profile of L5 A7 A5 L6 A8 A6 L8 L7 against normal blind 7
sketch "Sketch21" plane through (0, -146.2556, 53.2327) normal (0, 0.9397, -0.342) x axis (-1, 0, 0)
  line L1 (45, -18.9002) -> (-45, -18.9002)
  line L2 (50, 6.0998) -> (50, -13.9002)
  line L3 (-45, 11.0998) -> (45, 11.0998)
  line L4 (-50, -13.9002) -> (-50, 6.0998)
  line L5 (-35, -10.9479) -> (35, -10.9479)
  line L6 (35, 5.0147) -> (-35, 5.0147)
  arc A1 centre (-45, -13.9002) radius 5 clockwise from (-45, -18.9002) to (-50, -13.9002)
  arc A2 centre (45, -13.9002) radius 5 clockwise from (50, -13.9002) to (45, -18.9002)
  arc A3 centre (45, 6.0998) radius 5 clockwise from (45, 11.0998) to (50, 6.0998)
  arc A4 centre (-45, 6.0998) radius 5 clockwise from (-50, 6.0998) to (-45, 11.0998)
  closed curve K1 centre (-35, -2.9666)
  closed curve K2 centre (35, -2.9666)
  circle C1 centre (-45, 6.0998) radius 1.5
  circle C2 centre (-45, -13.9002) radius 1.5
  circle C3 centre (45, 6.0998) radius 1.5
  circle C4 centre (45, -13.9002) radius 1.5
  concentric A4 C1
  concentric A1 C2
  concentric A3 C3
  concentric A2 C4
  dimension "d104" diameter C1 = 3
  dimension "d105" diameter C2 = 3
  dimension "d106" diameter C3 = 3
  dimension "d107" diameter C4 = 3
extrude "Extrude19" cut sketch "Sketch21" profile of C1 C2 C3 C4 against normal blind 10
sketch "Sketch22" plane through (0, -146.2556, 53.2327) normal (0, 0.9397, -0.342) x axis (-1, 0, 0)
  line L1 (-35, -10.9479) -> (35, -10.9479)
  line L2 (35, 5.0147) -> (-35, 5.0147)
  line L3 (45, -18.9002) -> (-45, -18.9002)
  line L4 (50, 6.0998) -> (50, -13.9002)
  line L5 (-45, 11.0998) -> (45, 11.0998)
  line L6 (-50, -13.9002) -> (-50, 6.0998)
  closed curve K1 centre (-35, -2.9666)
  closed curve K2 centre (35, -2.9666)
  arc A1 centre (-45, -13.9002) radius 5 clockwise from (-45, -18.9002) to (-50, -13.9002)
  arc A2 centre (45, -13.9002) radius 5 clockwise from (50, -13.9002) to (45, -18.9002)
  arc A3 centre (45, 6.0998) radius 5 clockwise from (45, 11.0998) to (50, 6.0998)
  arc A4 centre (-45, 6.0998) radius 5 clockwise from (-50, 6.0998) to (-45, 11.0998)
  circle C1 centre (45, 6.0998) radius 1.5
  circle C2 centre (-45, 6.0998) radius 1.5
  circle C3 centre (45, -13.9002) radius 1.5
  circle C4 centre (-45, -13.9002) radius 1.5
sketch "Sketch30" plane through (0, -160.351, 58.363) normal (0, 0.9397, -0.342) x axis (-1, 0, 0)
  line L1 (-47, 6.0998) -> (-47, -13.9002)
  line L2 (45, 8.0998) -> (-45, 8.0998)
  line L3 (47, -13.9002) -> (47, 6.0998)
  line L4 (-45, -15.9002) -> (45, -15.9002)
  line L5 (50, 6.0998) -> (50, -13.9002)
  line L6 (-45, 11.0998) -> (45, 11.0998)
  line L7 (-50, -13.9002) -> (-50, 6.0998)
  line L8 (45, -18.9002) -> (-45, -18.9002)
  line L9 (-45, 4.5998) -> (-47, 4.5998)
  line L10 (-43.5, 6.0998) -> (-43.5, 8.0998)
  line L11 (-45, -12.4002) -> (-47, -12.4002)
  line L12 (-43.5, -13.9002) -> (-43.5, -15.9002)
  line L13 (0, -15.9002) -> (0, 8.0998)
  line L14 (45, 4.5998) -> (47, 4.5998)
  line L15 (43.5, 6.0998) -> (43.5, 8.0998)
  line L16 (45, -12.4002) -> (47, -12.4002)
  line L17 (43.5, -13.9002) -> (43.5, -15.9002)
  arc A1 centre (-45, 6.0998) radius 2 clockwise from (-47, 6.0998) to (-45, 8.0998)
  arc A2 centre (45, 6.0998) radius 2 clockwise from (45, 8.0998) to (47, 6.0998)
  arc A3 centre (45, -13.9002) radius 2 clockwise from (47, -13.9002) to (45, -15.9002)
  arc A4 centre (-45, -13.9002) radius 2 clockwise from (-45, -15.9002) to (-47, -13.9002)
  arc A5 centre (45, -13.9002) radius 5 clockwise from (50, -13.9002) to (45, -18.9002)
  arc A6 centre (45, 6.0998) radius 5 clockwise from (45, 11.0998) to (50, 6.0998)
  arc A7 centre (-45, 6.0998) radius 5 clockwise from (-50, 6.0998) to (-45, 11.0998)
  arc A8 centre (-45, -13.9002) radius 5 clockwise from (-45, -18.9002) to (-50, -13.9002)
  circle C1 centre (-45, 6.0998) radius 1.5
  circle C2 centre (-45, -13.9002) radius 1.5
  circle C3 centre (45, 6.0998) radius 1.5
  circle C4 centre (45, -13.9002) radius 1.5
  point P26 (-47, 4.5998)
  point P27 (-45, 4.5998)
  point P28 (-43.5, 8.0998)
  point P29 (-43.5, 6.0998)
  point P30 (-47, -12.4002)
  point P32 (-43.5, -15.9002)
  point P31 (-45, -12.4002)
  point P33 (-43.5, -13.9002)
  point P34 (0, 8.0998)
  point P35 (0, -15.9002)
  point P36 (47, 4.5998)
  point P37 (45, 4.5998)
  point P38 (43.5, 8.0998)
  point P39 (43.5, 6.0998)
  point P40 (47, -12.4002)
  point P41 (45, -12.4002)
  point P42 (43.5, -15.9002)
  point P43 (43.5, -13.9002)
  coincident L1 P26
  perpendicular L1 L9
  coincident C1 P27
  tangent C1 L9
  coincident L2 P28
  perpendicular L2 L10
  coincident C1 P29
  tangent C1 L10
  coincident L1 P30
  perpendicular L1 L11
  coincident L4 P32
  perpendicular L4 L12
  coincident C2 P31
  coincident C2 P33
  tangent C2 L11
  tangent C2 L12
  midpoint L2 P34
  midpoint L4 P35
  symmetric P26 L13 P36
  symmetric P27 L13 P37
  symmetric P28 L13 P38
  symmetric P29 L13 P39
  symmetric P30 L13 P40
  symmetric P31 L13 P41
  symmetric P32 L13 P42
  symmetric P33 L13 P43
extrude "Extrude20" add sketch "Sketch30" profile of L1 A1 L2 A2 L3 A3 L4 A4 C1 C2 C3 C4 L9 L10 L11 L12 L14 L15 L16 L17 against normal blind 15
offset_faces "OffsetFaces1" distance 2
sketch "Sketch31" plane through (0, -160.351, 58.363) normal (0, 0.9397, -0.342) x axis (-1, 0, 0)
  line L1 (-47, 2.5998) -> (-47, -10.4002)
  line L2 (-45, 2.5998) -> (-47, 2.5998)
  line L3 (-41.5, 8.0998) -> (-41.5, 6.0998)
  line L4 (41.5, 8.0998) -> (-41.5, 8.0998)
  line L5 (41.5, 6.0998) -> (41.5, 8.0998)
  line L6 (47, 2.5998) -> (45, 2.5998)
  line L7 (47, -10.4002) -> (47, 2.5998)
  line L8 (45, -10.4002) -> (47, -10.4002)
  line L9 (41.5, -15.9002) -> (41.5, -13.9002)
  line L10 (-41.5, -15.9002) -> (41.5, -15.9002)
  line L11 (-41.5, -13.9002) -> (-41.5, -15.9002)
  line L12 (-47, -10.4002) -> (-45, -10.4002)
  line L13 (50, 6.0998) -> (50, -13.9002)
  line L14 (-45, 11.0998) -> (45, 11.0998)
  line L15 (-50, -13.9002) -> (-50, 6.0998)
  line L16 (45, -18.9002) -> (-45, -18.9002)
  line L17 (47, 8.0998) -> (-47, 8.0998)
  line L18 (47, -15.9002) -> (47, 8.0998)
  line L19 (-47, -15.9002) -> (47, -15.9002)
  line L20 (-47, 8.0998) -> (-47, -15.9002)
  arc A1 centre (-45, 6.0998) radius 3.5 clockwise from (-41.5, 6.0998) to (-45, 2.5998)
  arc A2 centre (45, 6.0998) radius 3.5 clockwise from (45, 2.5998) to (41.5, 6.0998)
  arc A3 centre (45, -13.9002) radius 3.5 clockwise from (41.5, -13.9002) to (45, -10.4002)
  arc A4 centre (-45, -13.9002) radius 3.5 clockwise from (-45, -10.4002) to (-41.5, -13.9002)
  arc A5 centre (45, -13.9002) radius 5 clockwise from (50, -13.9002) to (45, -18.9002)
  arc A6 centre (45, 6.0998) radius 5 clockwise from (45, 11.0998) to (50, 6.0998)
  arc A7 centre (-45, 6.0998) radius 5 clockwise from (-50, 6.0998) to (-45, 11.0998)
  arc A8 centre (-45, -13.9002) radius 5 clockwise from (-45, -18.9002) to (-50, -13.9002)
  horizontal L17
  vertical L18
  horizontal L19
  vertical L20
  collinear L7 L18
  collinear L4 L17
  collinear L10 L19
  collinear L1 L20
extrude "Extrude21" cut sketch "Sketch31" profile of L2 A1 L3 L5 A2 L6 L8 A3 L9 L11 A4 L12 L17 L18 L19 L20 against normal blind 2
extrude "Extrude22" cut of existing geometry blind -3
